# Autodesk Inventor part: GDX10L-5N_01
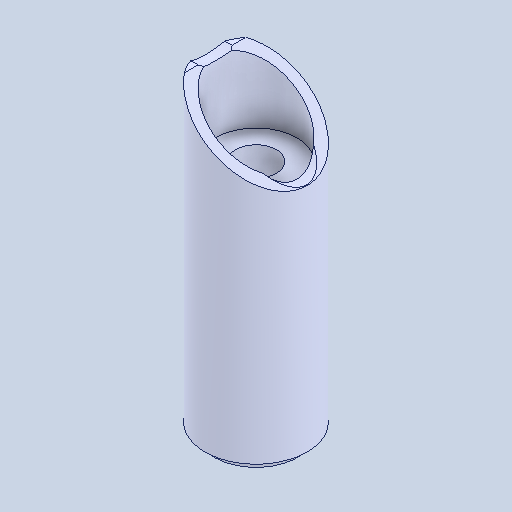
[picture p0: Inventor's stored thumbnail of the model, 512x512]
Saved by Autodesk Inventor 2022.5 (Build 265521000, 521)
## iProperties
Created: 2024-06
Part Number: GDX10L-5N_01
Material: 一般
Document SubType Name: Modeling
Designer: ImaoCorp
Density: 1 g/cm^3
Appearance: 既定
Author: ImaoCorp
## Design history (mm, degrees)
feature "GDX10L-5N_01"
node "ソリッド1"
